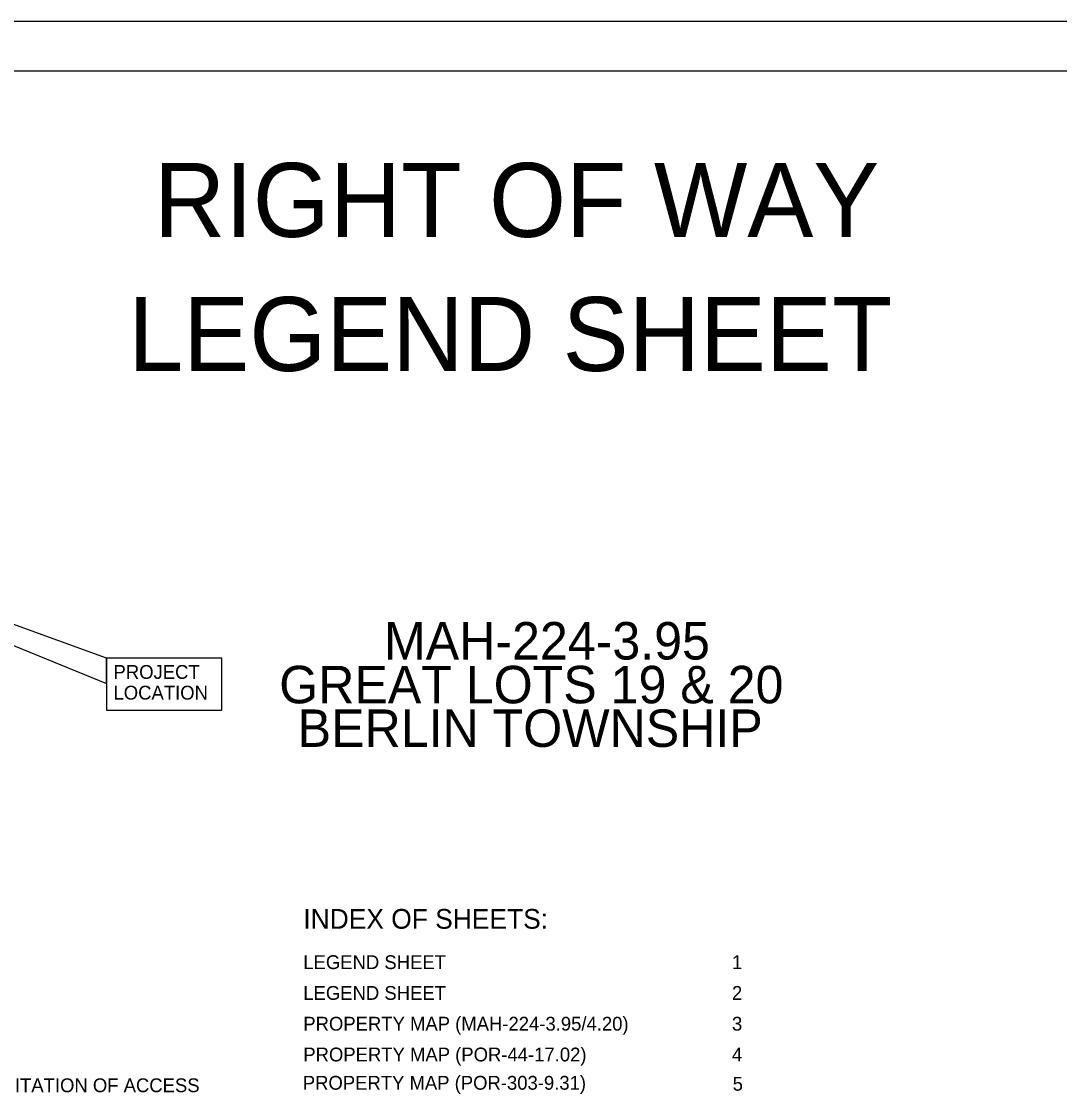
# Model space of a CAD drawing. Extents: x 0 to 34, y 0 to 22.
# Drawn here: x 10.89 to 21.41, y 11.1 to 22 of the extents above; entities that cross this region are included whole.
import ezdxf

# ---------------------------------------------------------------- set-up
doc = ezdxf.new("R2010")
doc.units = 0
for name, color, linetype in [('SH_Border', 7, 'Continuous'), ('SH_Cut_Line', 7, 'Continuous'), ('SH_Data', 7, 'Continuous'), ('SH_Text', 7, 'Continuous')]:
    doc.layers.add(name, color=color, linetype=linetype)

msp = doc.modelspace()

# ---------------------------------------------------------------- linework, layer by layer
at = {"layer": 'SH_Border'}
msp.add_lwpolyline([(1.5, 21.5), (33.5, 21.5), (33.5, 0.5), (1.5, 0.5)], close=True, dxfattribs=at)
at = {"layer": 'SH_Cut_Line'}
msp.add_lwpolyline([(0, 0), (34, 0), (34, 22), (0, 22)], close=True, dxfattribs=at)
at = {"layer": 'SH_Text'}
for points in [[(11.748, 15.546), (6.129, 17.583), (11.748, 15.289)], [(11.748, 15.018), (12.917, 15.018), (12.917, 15.546), (11.748, 15.546)]]:
    msp.add_lwpolyline(points, close=True, dxfattribs=at)

# ---------------------------------------------------------------- texts
at = {"layer": 'SH_Data'}
for s, height, p in [('RIGHT OF WAY', 0.75, (12.227, 19.816)), ('LEGEND SHEET', 0.75, (11.968, 18.457)), ('MAH-224-3.95', 0.38, (14.56, 15.532)), ('GREAT LOTS 19 & 20', 0.38, (13.498, 15.088)), ('BERLIN TOWNSHIP', 0.38, (13.685, 14.646)), ('INDEX OF SHEETS:', 0.2, (13.742, 12.803)), ('LEGEND SHEET                       ', 0.14, (13.742, 12.394)), ('1     ', 0.14, (18.088, 12.394)), ('LEGEND SHEET', 0.14, (13.742, 12.082)), ('2     ', 0.14, (18.088, 12.082)), ('PROPERTY MAP (MAH-224-3.95/4.20)', 0.14, (13.742, 11.77)), ('3     ', 0.14, (18.088, 11.77)), ('PROPERTY MAP (POR-44-17.02)', 0.14, (13.742, 11.458)), ('4', 0.14, (18.088, 11.458)), ('PROPERTY MAP (POR-303-9.31)', 0.14, (13.737, 11.171)), ('5', 0.14, (18.095, 11.161))]:
    msp.add_text(s, height=height, dxfattribs=at).set_placement(p)
at = {"layer": 'SH_Text'}
for s, p in [('PROJECT', (11.818, 15.336)), ('LOCATION', (11.818, 15.126)), ('WL = FEE SIMPLE WITH LIMITATION OF ACCESS', (8.327, 11.146))]:
    msp.add_text(s, height=0.14, dxfattribs=at).set_placement(p)

doc.saveas('drawing.dxf')
